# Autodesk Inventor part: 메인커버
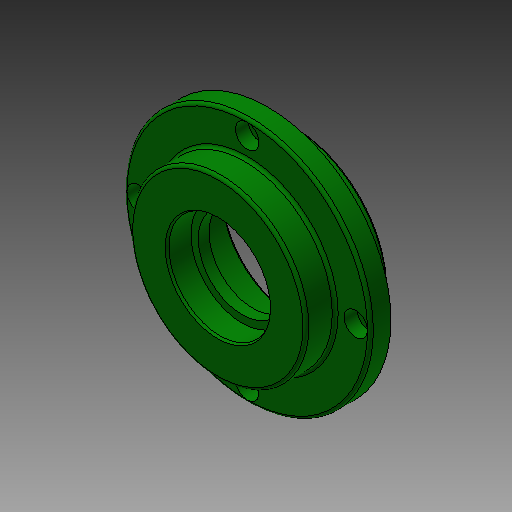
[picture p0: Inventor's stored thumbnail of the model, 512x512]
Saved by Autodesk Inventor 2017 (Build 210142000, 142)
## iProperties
Created: 2018-09
Part Number: 메인커버
Material: 알루미늄 6061
Document SubType Name: Modeling
Designer: mduedu
Density: 2.71 g/cm^3
Appearance: 진녹색
Mass: 164.611 g
Surface Area: 184.933 cm^2
Volume: 60.742 cm^3
Author: mduedu
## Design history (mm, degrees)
sketch "스케치1"
  geometry: C1 r 42 at (0, 0); 1 further point
  constraints: 1 centre point, 1 coincident
  dimensions: "d34" = 84 diameter of C1
extrude "돌출1" new body sketch "스케치1" distance "d2" = 7; taper "d3" = 0 deg
sketch "스케치2"
  geometry: C1 r 30 at (0, 0); 1 further point
  constraints: 1 centre point, 1 coincident
  dimensions: "d4" = 60 diameter of C1
extrude "돌출2" join sketch "스케치2" distance "d5" = 10; taper "d6" = 0 deg
sketch "스케치3"
  geometry: C1 r 32.5 at (0, 0); 1 further point
  constraints: 1 centre point, 1 coincident
  dimensions: "d7" = 65 diameter of C1
extrude "돌출3" join sketch "스케치3" distance "d8" = 9; taper "d9" = 0 deg
sketch "스케치4"
  geometry: L1 (-32.5, -9)-(32.5, -9) reference; L2 (30, 17)-(-30, 17) reference; L3 (0, 17)-(0, -9); L4 (0, -9)-(23.5, -9); L5 (23.5, -9)-(23.5, 5); L6 (23.5, 5)-(0, 5); L7 (0, 5)-(0, -9); L8 (0, 5)-(15, 5); L9 (15, 5)-(15, 8.7); L10 (15, 8.7)-(0, 8.7); L11 (0, 8.7)-(0, 5); L12 (0, 8.7)-(17.5, 8.7); L13 (17.5, 8.7)-(17.5, 17); L14 (17.5, 17)-(0, 17); L15 (0, 17)-(0, 8.7); 1 further point
  constraints: 26 end point, 6 parallel, 3 horizontal, 3 perpendicular, 2 midpoint, 1 point on line
  dimensions: "d10" = 14 distance of L4.end L5.end; "d12" = 8.3 distance of L12.end L13.end; "d13" = 35 diameter of L13 L3; "d14" = 30 diameter of L9 L3; "d15" = 47 diameter of L5 L3
revolve "회전1" sketch "스케치4" stored, may be unused: angle "d16" = 90 deg
fillet "모깎기2" dims "d18" = 1
fillet "모깎기3" dims "d19" = 1
chamfer "모따기1" distance "d20" = 0.8; stored, may be unused: second distance "d21" = 2, angle "d22" = 30 deg
chamfer "모따기2" distance "d23" = 1; stored, may be unused: second distance "d24" = 2, angle "d25" = 30 deg
fillet "모깎기4" dims "d26" = 0.3
sketch "스케치5" dims "d35" = 74
  geometry: 3 further points
  constraints: 2 vertical alignment, 1 coincident, 2 other
hole "구멍1" sketch "스케치5" at (0, 37) diameter "d27" = 4.5; stored, may be unused: countersink angle "d31" = 90 deg, drill point angle "d33" = 118 deg; dims "d28" = 6, "d29" = 8, "d30" = 4.4, "d32" = 8
node "솔리드1"
pattern_circular "원형 패턴1" dims angle "d38" = 360 deg
